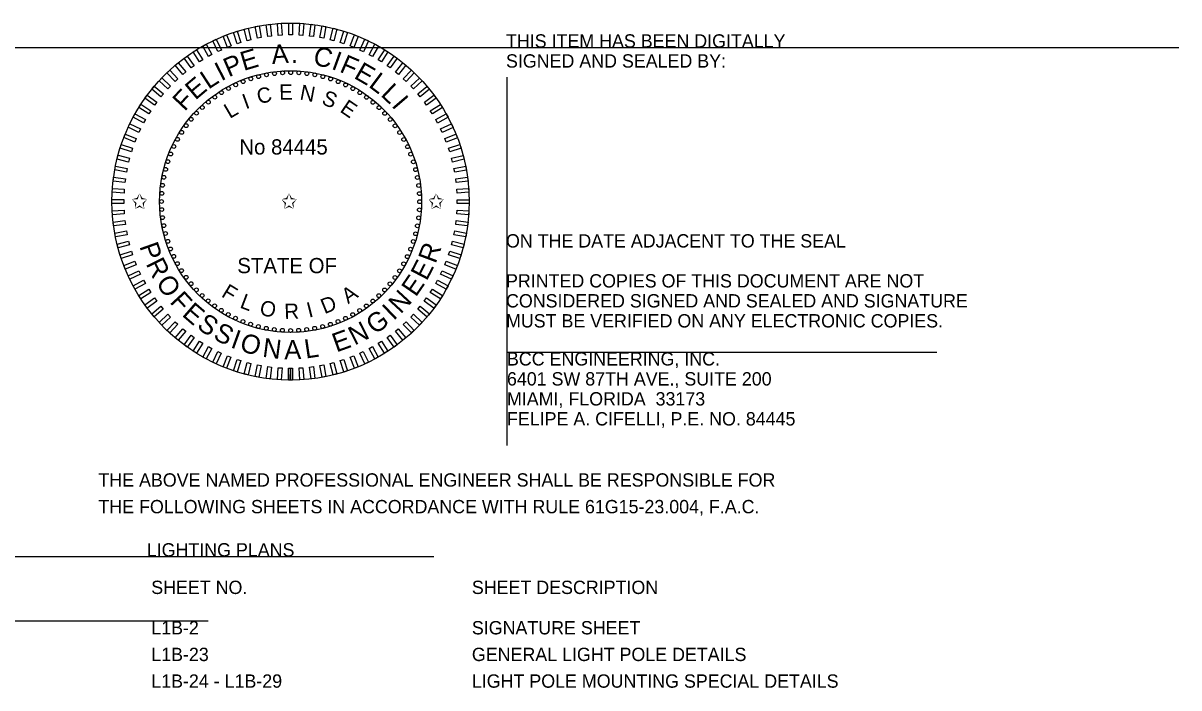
# Model space of a CAD drawing. Extents: x -811.2 to -767.6, y -2295.2 to -2235.1.
# Drawn here: x -802.94 to -796.87, y -2238.99 to -2235.5 of the extents above; entities that cross this region are included whole.
import ezdxf

# ---------------------------------------------------------------- set-up
doc = ezdxf.new("R2010")
doc.units = 0
for name, color, linetype in [('AdhocPoint_dp', 7, 'Continuous'), ('PlotBorder_dp', 7, 'Continuous'), ('TextMinor', 7, 'Continuous'), ('TextMisc', 7, 'Continuous'), ('TextShtNo', 7, 'Continuous')]:
    doc.layers.add(name, color=color, linetype=linetype)

msp = doc.modelspace()

# ---------------------------------------------------------------- linework, layer by layer
at = {"layer": 'AdhocPoint_dp'}
for p, q in [((-808.3596, -2235.6292), (-796.8708, -2235.6292)), ((-800.3974, -2235.7843), (-800.3974, -2237.719)), ((-800.3974, -2237.229), (-798.1407, -2237.229)), ((-809.3854, -2238.3022), (-800.7818, -2238.3022)), ((-801.9648, -2238.6414), (-810.4432, -2238.6414))]:
    msp.add_line(p, q, dxfattribs=at)
at = {"layer": 'TextMinor'}
for radius in [0.9375, 0.6875]:
    msp.add_circle((-801.5329, -2236.4379), radius, dxfattribs=at)
at = {"layer": 'TextShtNo'}
for p, q in [((-801.5429, -2237.3754), (-801.5431, -2237.3129)), ((-801.5329, -2237.3754), (-801.5331, -2237.3129)), ((-801.5229, -2237.3754), (-801.5231, -2237.3129))]:
    msp.add_line(p, q, dxfattribs=at)
for points in [[(-801.6869, -2235.5764), (-801.7067, -2235.5802), (-801.7184, -2235.5189), (-801.6986, -2235.5151)], [(-801.6325, -2235.5685), (-801.6525, -2235.571), (-801.6603, -2235.5091), (-801.6403, -2235.5065)], [(-801.5777, -2235.5639), (-801.5978, -2235.5652), (-801.6018, -2235.5029), (-801.5816, -2235.5016)], [(-801.5227, -2235.5629), (-801.5429, -2235.5629), (-801.5429, -2235.5004), (-801.5227, -2235.5004)], [(-801.4678, -2235.5652), (-801.488, -2235.564), (-801.484, -2235.5016), (-801.4639, -2235.5029)], [(-801.4131, -2235.571), (-801.4332, -2235.5685), (-801.4254, -2235.5066), (-801.4053, -2235.5091)], [(-801.359, -2235.5803), (-801.3788, -2235.5765), (-801.3671, -2235.5152), (-801.3473, -2235.5189)], [(-801.8456, -2235.6206), (-801.8643, -2235.628), (-801.8873, -2235.5699), (-801.8686, -2235.5625)], [(-801.7936, -2235.6025), (-801.8128, -2235.6088), (-801.8321, -2235.5494), (-801.8129, -2235.5432)], [(-801.7407, -2235.5878), (-801.7602, -2235.5928), (-801.7758, -2235.5324), (-801.7562, -2235.5273)], [(-801.3054, -2235.5929), (-801.325, -2235.5879), (-801.3095, -2235.5274), (-801.2899, -2235.5324)], [(-801.2528, -2235.6088), (-801.272, -2235.6026), (-801.2527, -2235.5432), (-801.2335, -2235.5494)], [(-801.2013, -2235.6281), (-801.2201, -2235.6206), (-801.1971, -2235.5626), (-801.1783, -2235.57)], [(-801.9455, -2235.6662), (-801.9632, -2235.6759), (-801.9933, -2235.6212), (-801.9756, -2235.6115)], [(-801.8963, -2235.6418), (-801.9145, -2235.6504), (-801.9411, -2235.5939), (-801.9229, -2235.5853)], [(-801.1511, -2235.6505), (-801.1694, -2235.6419), (-801.1428, -2235.5854), (-801.1246, -2235.594)], [(-801.1025, -2235.676), (-801.1201, -2235.6663), (-801.0901, -2235.6116), (-801.0724, -2235.6213)], [(-802.039, -2235.724), (-802.0553, -2235.7359), (-802.092, -2235.6853), (-802.0757, -2235.6735)], [(-801.9932, -2235.6936), (-802.0102, -2235.7044), (-802.0437, -2235.6517), (-802.0266, -2235.6409)], [(-801.0555, -2235.7045), (-801.0725, -2235.6937), (-801.039, -2235.641), (-801.022, -2235.6518)], [(-801.0104, -2235.736), (-801.0267, -2235.7241), (-800.99, -2235.6736), (-800.9737, -2235.6854)], [(-802.1245, -2235.793), (-802.1392, -2235.8069), (-802.182, -2235.7613), (-802.1672, -2235.7475)], [(-802.0828, -2235.7572), (-802.0984, -2235.77), (-802.1382, -2235.7219), (-802.1226, -2235.7091)], [(-800.9673, -2235.7702), (-800.9829, -2235.7573), (-800.9431, -2235.7092), (-800.9275, -2235.722)], [(-800.9265, -2235.807), (-800.9412, -2235.7932), (-800.8985, -2235.7477), (-800.8838, -2235.7615)], [(-802.1638, -2235.8315), (-802.1776, -2235.8462), (-802.2232, -2235.8034), (-802.2093, -2235.7887)], [(-800.8881, -2235.8463), (-800.9019, -2235.8316), (-800.8564, -2235.7889), (-800.8426, -2235.8036)], [(-802.2349, -2235.9153), (-802.2467, -2235.9316), (-802.2972, -2235.8949), (-802.2854, -2235.8786)], [(-802.2007, -2235.8723), (-802.2135, -2235.8878), (-802.2616, -2235.848), (-802.2488, -2235.8325)], [(-800.8522, -2235.888), (-800.8651, -2235.8724), (-800.817, -2235.8326), (-800.8041, -2235.8482)], [(-800.819, -2235.9318), (-800.8309, -2235.9155), (-800.7804, -2235.8788), (-800.7685, -2235.8951)], [(-802.2663, -2235.9604), (-802.2771, -2235.9775), (-802.3298, -2235.944), (-802.319, -2235.927)], [(-800.7887, -2235.9776), (-800.7995, -2235.9606), (-800.7468, -2235.9271), (-800.7359, -2235.9442)], [(-802.2948, -2236.0074), (-802.3045, -2236.0251), (-802.3593, -2235.995), (-802.3495, -2235.9773)], [(-800.7612, -2236.0253), (-800.7709, -2236.0076), (-800.7162, -2235.9775), (-800.7065, -2235.9952)], [(-802.3203, -2236.0561), (-802.3289, -2236.0744), (-802.3854, -2236.0478), (-802.3768, -2236.0295)], [(-800.7368, -2236.0745), (-800.7454, -2236.0563), (-800.6889, -2236.0297), (-800.6803, -2236.048)], [(-802.3428, -2236.1063), (-802.3502, -2236.1251), (-802.4082, -2236.1021), (-802.4008, -2236.0833)], [(-800.7156, -2236.1252), (-800.723, -2236.1065), (-800.665, -2236.0835), (-800.6575, -2236.1023)], [(-802.362, -2236.1578), (-802.3682, -2236.177), (-802.4276, -2236.1577), (-802.4214, -2236.1385)], [(-800.6976, -2236.1772), (-800.7038, -2236.158), (-800.6444, -2236.1387), (-800.6382, -2236.1579)], [(-802.3779, -2236.2104), (-802.383, -2236.23), (-802.4434, -2236.2144), (-802.4384, -2236.1949)], [(-800.6829, -2236.2301), (-800.6879, -2236.2106), (-800.6274, -2236.1951), (-800.6224, -2236.2146)], [(-802.3905, -2236.2639), (-802.3943, -2236.2837), (-802.4557, -2236.272), (-802.4519, -2236.2522)], [(-800.6715, -2236.2839), (-800.6753, -2236.2641), (-800.6139, -2236.2524), (-800.6102, -2236.2722)], [(-802.3998, -2236.3181), (-802.4023, -2236.3381), (-802.4643, -2236.3303), (-802.4617, -2236.3103)], [(-800.6635, -2236.3383), (-800.666, -2236.3183), (-800.6041, -2236.3105), (-800.6016, -2236.3305)], [(-802.4056, -2236.3728), (-802.4069, -2236.3929), (-802.4692, -2236.389), (-802.4679, -2236.3689)], [(-800.659, -2236.3931), (-800.6603, -2236.373), (-800.5979, -2236.369), (-800.5967, -2236.3892)], [(-802.408, -2236.4277), (-802.408, -2236.4479), (-802.4704, -2236.4479), (-802.4704, -2236.4277)], [(-802.4069, -2236.4827), (-802.4056, -2236.5028), (-802.4679, -2236.5067), (-802.4692, -2236.4866)], [(-800.6603, -2236.503), (-800.659, -2236.4829), (-800.5967, -2236.4868), (-800.5979, -2236.5069)], [(-800.6579, -2236.4481), (-800.6579, -2236.4279), (-800.5955, -2236.4279), (-800.5955, -2236.4481)], [(-802.4023, -2236.5375), (-802.3998, -2236.5575), (-802.4618, -2236.5653), (-802.4643, -2236.5453)], [(-800.6661, -2236.5577), (-800.6635, -2236.5376), (-800.6016, -2236.5455), (-800.6041, -2236.5655)], [(-802.3944, -2236.5918), (-802.3906, -2236.6117), (-802.4519, -2236.6234), (-802.4557, -2236.6035)], [(-800.6753, -2236.6119), (-800.6715, -2236.592), (-800.6102, -2236.6037), (-800.614, -2236.6236)], [(-802.383, -2236.6456), (-802.378, -2236.6652), (-802.4385, -2236.6807), (-802.4435, -2236.6612)], [(-800.6879, -2236.6654), (-800.6829, -2236.6458), (-800.6224, -2236.6613), (-800.6274, -2236.6809)], [(-802.3683, -2236.6986), (-802.362, -2236.7178), (-802.4214, -2236.7371), (-802.4277, -2236.7179)], [(-800.7039, -2236.718), (-800.6976, -2236.6988), (-800.6382, -2236.7181), (-800.6445, -2236.7373)], [(-802.3503, -2236.7505), (-802.3428, -2236.7693), (-802.4009, -2236.7923), (-802.4083, -2236.7735)], [(-800.7231, -2236.7695), (-800.7157, -2236.7507), (-800.6576, -2236.7737), (-800.665, -2236.7925)], [(-802.329, -2236.8012), (-802.3204, -2236.8195), (-802.3769, -2236.8461), (-802.3855, -2236.8278)], [(-802.3046, -2236.8505), (-802.2949, -2236.8682), (-802.3496, -2236.8983), (-802.3593, -2236.8806)], [(-800.7455, -2236.8197), (-800.7369, -2236.8014), (-800.6804, -2236.828), (-800.689, -2236.8463)], [(-802.2772, -2236.8982), (-802.2664, -2236.9152), (-802.3191, -2236.9487), (-802.3299, -2236.9316)], [(-800.7996, -2236.9154), (-800.7888, -2236.8983), (-800.736, -2236.9318), (-800.7469, -2236.9488)], [(-800.771, -2236.8684), (-800.7613, -2236.8507), (-800.7066, -2236.8808), (-800.7163, -2236.8984)], [(-802.2468, -2236.944), (-802.235, -2236.9603), (-802.2855, -2236.997), (-802.2973, -2236.9807)], [(-800.831, -2236.9605), (-800.8191, -2236.9441), (-800.7686, -2236.9808), (-800.7805, -2236.9972)], [(-802.2136, -2236.9878), (-802.2008, -2237.0034), (-802.2489, -2237.0432), (-802.2618, -2237.0276)], [(-802.1778, -2237.0295), (-802.1639, -2237.0442), (-802.2095, -2237.0869), (-802.2233, -2237.0722)], [(-800.902, -2237.0443), (-800.8882, -2237.0296), (-800.8427, -2237.0723), (-800.8565, -2237.0871)], [(-800.8652, -2237.0035), (-800.8523, -2236.9879), (-800.8042, -2237.0278), (-800.8171, -2237.0433)], [(-802.1394, -2237.0688), (-802.1246, -2237.0826), (-802.1674, -2237.1281), (-802.1821, -2237.1143)], [(-800.9414, -2237.0827), (-800.9266, -2237.0689), (-800.8839, -2237.1144), (-800.8986, -2237.1282)], [(-802.0985, -2237.1056), (-802.083, -2237.1185), (-802.1228, -2237.1666), (-802.1383, -2237.1537)], [(-802.0555, -2237.1398), (-802.0392, -2237.1517), (-802.0759, -2237.2022), (-802.0922, -2237.1903)], [(-801.0268, -2237.1518), (-801.0105, -2237.1399), (-800.9738, -2237.1904), (-800.9901, -2237.2023)], [(-800.983, -2237.1186), (-800.9675, -2237.1057), (-800.9277, -2237.1538), (-800.9432, -2237.1667)], [(-802.0104, -2237.1712), (-801.9933, -2237.1821), (-802.0268, -2237.2348), (-802.0438, -2237.224)], [(-801.9634, -2237.1998), (-801.9457, -2237.2095), (-801.9758, -2237.2642), (-801.9935, -2237.2545)], [(-801.1203, -2237.2096), (-801.1026, -2237.1999), (-801.0725, -2237.2546), (-801.0902, -2237.2643)], [(-801.0727, -2237.1822), (-801.0556, -2237.1713), (-801.0222, -2237.2241), (-801.0392, -2237.2349)], [(-801.9147, -2237.2253), (-801.8964, -2237.2339), (-801.923, -2237.2904), (-801.9413, -2237.2818)], [(-801.8645, -2237.2477), (-801.8457, -2237.2552), (-801.8687, -2237.3132), (-801.8875, -2237.3058)], [(-801.813, -2237.2669), (-801.7938, -2237.2732), (-801.8131, -2237.3326), (-801.8323, -2237.3263)], [(-801.2722, -2237.2732), (-801.253, -2237.267), (-801.2337, -2237.3264), (-801.2529, -2237.3326)], [(-801.2203, -2237.2552), (-801.2015, -2237.2478), (-801.1785, -2237.3058), (-801.1973, -2237.3133)], [(-801.1696, -2237.234), (-801.1513, -2237.2254), (-801.1247, -2237.2819), (-801.143, -2237.2905)], [(-801.7604, -2237.2829), (-801.7409, -2237.2879), (-801.7564, -2237.3484), (-801.7759, -2237.3434)], [(-801.7069, -2237.2955), (-801.6871, -2237.2993), (-801.6988, -2237.3606), (-801.7186, -2237.3568)], [(-801.6527, -2237.3047), (-801.6327, -2237.3073), (-801.6405, -2237.3692), (-801.6605, -2237.3667)], [(-801.598, -2237.3106), (-801.5779, -2237.3118), (-801.5818, -2237.3741), (-801.602, -2237.3729)], [(-801.5431, -2237.3129), (-801.5229, -2237.3129), (-801.5229, -2237.3754), (-801.5431, -2237.3754)], [(-801.4881, -2237.3118), (-801.468, -2237.3106), (-801.4641, -2237.3729), (-801.4842, -2237.3741)], [(-801.4334, -2237.3073), (-801.4133, -2237.3048), (-801.4055, -2237.3667), (-801.4255, -2237.3692)], [(-801.379, -2237.2993), (-801.3591, -2237.2955), (-801.3474, -2237.3569), (-801.3673, -2237.3607)], [(-801.3252, -2237.288), (-801.3056, -2237.2829), (-801.2901, -2237.3434), (-801.3097, -2237.3484)]]:
    msp.add_lwpolyline(points, close=True, dxfattribs=at)
for centre in [(-801.6173, -2235.7657), (-801.5749, -2235.7617), (-801.5324, -2235.7604), (-801.4898, -2235.7618), (-801.4475, -2235.7658), (-801.8209, -2235.8247), (-801.7818, -2235.8078), (-801.7417, -2235.7934), (-801.7009, -2235.7816), (-801.6593, -2235.7723), (-801.4054, -2235.7725), (-801.3639, -2235.7818), (-801.323, -2235.7938), (-801.283, -2235.8082), (-801.244, -2235.8251), (-801.9307, -2235.8895), (-801.8955, -2235.8656), (-801.8588, -2235.8439), (-801.2061, -2235.8445), (-801.1694, -2235.8662), (-801.9963, -2235.9436), (-801.9643, -2235.9155), (-801.1343, -2235.8901), (-801.1007, -2235.9163), (-801.0688, -2235.9444), (-802.0546, -2236.0056), (-802.0264, -2235.9737), (-801.0387, -2235.9745), (-801.0106, -2236.0065), (-802.0807, -2236.0392), (-800.9845, -2236.0401), (-802.1263, -2236.111), (-802.1046, -2236.0744), (-800.9606, -2236.0754), (-800.939, -2236.112), (-802.1626, -2236.188), (-802.1457, -2236.1489), (-800.9197, -2236.1499), (-800.9028, -2236.189), (-802.1771, -2236.228), (-800.8884, -2236.2291), (-802.1983, -2236.3104), (-802.189, -2236.2689), (-800.8766, -2236.27), (-800.8674, -2236.3115), (-802.205, -2236.3524), (-800.8607, -2236.3535), (-802.209, -2236.3948), (-800.8568, -2236.3959), (-802.2104, -2236.4373), (-802.2091, -2236.4799), (-800.8568, -2236.481), (-800.8555, -2236.4385), (-802.2051, -2236.5222), (-800.8609, -2236.5234), (-802.1985, -2236.5643), (-802.1893, -2236.6058), (-800.8769, -2236.6069), (-800.8676, -2236.5654), (-802.1774, -2236.6467), (-800.8888, -2236.6478), (-802.163, -2236.6868), (-802.1462, -2236.7258), (-800.9202, -2236.7269), (-800.9032, -2236.6878), (-802.1269, -2236.7638), (-800.9395, -2236.7648), (-802.1052, -2236.8004), (-802.0813, -2236.8356), (-800.9852, -2236.8366), (-800.9612, -2236.8014), (-802.0553, -2236.8693), (-802.0272, -2236.9012), (-801.0395, -2236.9021), (-801.0113, -2236.8702), (-801.9971, -2236.9314), (-801.9652, -2236.9595), (-801.1015, -2236.9602), (-801.0696, -2236.9321), (-801.9316, -2236.9856), (-801.8964, -2237.0096), (-801.8598, -2237.0313), (-801.207, -2237.0318), (-801.1704, -2237.0102), (-801.1352, -2236.9863), (-801.8219, -2237.0506), (-801.7828, -2237.0676), (-801.7428, -2237.082), (-801.702, -2237.0939), (-801.365, -2237.0942), (-801.3241, -2237.0824), (-801.2841, -2237.068), (-801.245, -2237.0511), (-801.6604, -2237.1033), (-801.6184, -2237.1099), (-801.576, -2237.114), (-801.5329, -2237.1154), (-801.4909, -2237.1141), (-801.4486, -2237.1101), (-801.4065, -2237.1035)]:
    msp.add_circle(centre, 0.01, dxfattribs=at)

# ---------------------------------------------------------------- texts
at = {"layer": 'PlotBorder_dp'}
for s, p in [('THIS ITEM HAS BEEN DIGITALLY', (-800.4024, -2235.6292)), ('SIGNED AND SEALED BY:', (-800.4024, -2235.7342)), ('ON THE DATE ADJACENT TO THE SEAL', (-800.4024, -2236.6792)), ('PRINTED COPIES OF THIS DOCUMENT ARE NOT ', (-800.4024, -2236.8892)), ('CONSIDERED SIGNED AND SEALED AND SIGNATURE ', (-800.4024, -2236.9942)), ('MUST BE VERIFIED ON ANY ELECTRONIC COPIES.', (-800.4024, -2237.0992)), ('BCC ENGINEERING, INC.', (-800.3974, -2237.299)), ('6401 SW 87TH AVE., SUITE 200', (-800.3974, -2237.404)), ('MIAMI, FLORIDA  33173', (-800.3974, -2237.509)), ('FELIPE A. CIFELLI, P.E. NO. 84445', (-800.3974, -2237.614)), ('THE ABOVE NAMED PROFESSIONAL ENGINEER SHALL BE RESPONSIBLE FOR ', (-802.5415, -2237.9352)), ('THE FOLLOWING SHEETS IN ACCORDANCE WITH RULE 61G15-23.004, F.A.C.', (-802.5415, -2238.0752)), ('LIGHTING PLANS', (-802.2878, -2238.3022))]:
    msp.add_text(s, height=0.07, dxfattribs=at).set_placement(p)
at = {"layer": 'TextMisc'}
for s, p in [('SHEET NO.', (-802.2643, -2238.4992)), ('SHEET DESCRIPTION', (-800.5815, -2238.4992)), ('L1B-2', (-802.2643, -2238.7114)), ('SIGNATURE SHEET', (-800.5815, -2238.7114)), ('L1B-23', (-802.2643, -2238.8514)), ('GENERAL LIGHT POLE DETAILS', (-800.5815, -2238.8514)), ('L1B-24 - L1B-29', (-802.2643, -2238.9914)), ('LIGHT POLE MOUNTING SPECIAL DETAILS', (-800.5815, -2238.9914))]:
    msp.add_text(s, height=0.07, dxfattribs=at).set_placement(p)
at = {"layer": 'TextShtNo'}
for s, height, rotation, p in [('E', 0.1, 16.54261, (-801.7793, -2235.7522)), ('A', 0.1, 4.42103, (-801.6298, -2235.7157)), ('C', 0.1, 347.7999, (-801.4192, -2235.7182)), ('P', 0.1, 23.28287, (-801.8581, -2235.7858)), ('.', 0.1, 356.65403, (-801.5313, -2235.7092)), ('I', 0.1, 340.0631, (-801.3234, -2235.74)), ('F', 0.1, 336.52991, (-801.2807, -2235.7543)), ('L', 0.1, 33.07918, (-801.9643, -2235.8507)), ('I', 0.1, 26.81606, (-801.8977, -2235.8071)), ('E', 0.1, 330.07956, (-801.2055, -2235.7869)), ('L', 0.1, 323.03732, (-801.1282, -2235.832)), ('E', 0.1, 40.12142, (-802.033, -2235.908)), ('L', 0.1, 316.7742, (-801.0645, -2235.8797)), ('F', 0.1, 46.57177, (-802.0894, -2235.9675)), ('I', 0.08, 20.01168, (-801.7686, -2235.9538)), ('C', 0.08, 12.20255, (-801.7007, -2235.9263)), ('E', 0.08, 0.41861, (-801.5926, -2235.9028)), ('N', 0.08, 349.29143, (-801.4883, -2235.9013)), ('S', 0.08, 337.02207, (-801.3753, -2235.9231)), ('I', 0.1, 310.51108, (-801.0064, -2235.9342)), ('L', 0.08, 30.40215, (-801.8521, -2236.0043)), ('E', 0.08, 325.86633, (-801.2786, -2235.9633)), ('P', 0.1, 289.40551, (-802.3276, -2236.6725)), ('R', 0.1, 69.5134, (-800.7727, -2236.7676)), ('R', 0.1, 296.14576, (-802.2946, -2236.7641)), ('E', 0.1, 62.47116, (-800.8189, -2236.8583)), ('O', 0.1, 303.96711, (-802.2431, -2236.8647)), ('E', 0.1, 55.42892, (-800.8758, -2236.9427)), ('F', 0.1, 312.62798, (-802.1708, -2236.9668)), ('F', 0.08, 328.72408, (-801.901, -2236.9345)), ('A', 0.08, 34.49917, (-801.2311, -2236.9773)), ('N', 0.1, 47.17876, (-800.9551, -2237.0317)), ('E', 0.1, 319.07833, (-802.1073, -2237.0351)), ('L', 0.08, 339.29159, (-801.8037, -2236.9936)), ('O', 0.08, 349.68206, (-801.699, -2237.0333)), ('I', 0.08, 14.20366, (-801.4369, -2237.0485)), ('D', 0.08, 22.01279, (-801.3549, -2237.0298)), ('R', 0.08, 2.33977, (-801.5645, -2237.0552)), ('G', 0.1, 35.11153, (-801.092, -2237.1394)), ('I', 0.1, 43.64556, (-800.9928, -2237.0662)), ('S', 0.1, 326.12056, (-802.0297, -2237.101)), ('S', 0.1, 333.193, (-801.9443, -2237.1572)), ('N', 0.1, 26.86136, (-801.1972, -2237.1954)), ('I', 0.1, 340.26543, (-801.8526, -2237.2023)), ('O', 0.1, 343.79863, (-801.8049, -2237.2206)), ('E', 0.1, 19.81912, (-801.2926, -2237.2309)), ('N', 0.1, 352.45949, (-801.6839, -2237.2526)), ('A', 0.1, 0.70966, (-801.5655, -2237.2659)), ('L', 0.1, 8.47665, (-801.4533, -2237.2627))]:
    msp.add_text(s, height=height, rotation=rotation, dxfattribs=at).set_placement(p)
for s, p in [('No 84445', (-801.8019, -2236.1907)), ('✩', (-802.3679, -2236.4758)), ('✩', (-801.5832, -2236.4758)), ('✩', (-800.8113, -2236.4758)), ('STATE OF', (-801.8126, -2236.8141))]:
    msp.add_text(s, height=0.08, dxfattribs=at).set_placement(p)

doc.saveas('drawing.dxf')
